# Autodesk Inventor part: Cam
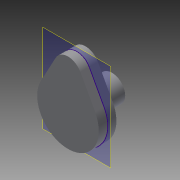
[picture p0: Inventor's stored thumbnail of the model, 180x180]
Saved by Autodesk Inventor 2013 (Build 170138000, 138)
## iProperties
Created: 2006-03
Part Number: Cam
Document SubType Name: Modeling
Designer: debonom
Mass: 14.1538 g
Surface Area: 42.5457 cm^2
Volume: 14.1538 cm^3
Density: 1 g/cm^3
Material: Generic
Author: debonom
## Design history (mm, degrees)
sketch "Sketch1"
  geometry: L1 (0, -26.6)-(0, 37.1) reference; L2 (-24.5, 0)-(24.5, 0) reference; L3 (-15.4, 8.312)-(-7.04, 23.8); L4 (7.04, 23.8)-(15.4, 8.312); A1 r 17.5 centre (0, 0) between (-15.4, 8.312) and (15.4, 8.312); A2 r 8 centre (0, 20) between (7.04, 23.8) and (-7.04, 23.8); 1 further point
  constraints: 4 end point, 4 point on circle, 4 tangent, 2 centre point, 1 coincident, 1 point on line
  dimensions: "d0" = 20 distance of point (0, 0) A2.centre; "d1" = 8 radius of A2; "d2" = 17.5 radius of A1
extrude "Extrusion1" new body sketch "Sketch1" distance "d3" = 10; taper "d4" = 0 deg
sketch "Sketch2"
  geometry: C1 r 7.5 at (0, 0); 1 further point
  constraints: 1 centre point, 1 coincident
  dimensions: "d5" = 15 diameter of C1
extrude "Extrusion2" join sketch "Sketch2" distance "d6" = 15; taper "d7" = 0 deg
workplane "Work Plane1"
sketch "Sketch3"
  geometry: L1 (-7.04, -23.8)-(-15.4, -8.312) reference; L2 (15.4, -8.312)-(7.04, -23.8) reference; A1 r 17.5 centre (0, 0) between (15.4, -8.312) and (-15.4, -8.312) reference; A2 r 8 centre (0, -20) between (-7.04, -23.8) and (7.04, -23.8) reference; 1 further point
  constraints: 4 end point, 4 point on circle, 2 centre point, 10 other
body "Solid1"
